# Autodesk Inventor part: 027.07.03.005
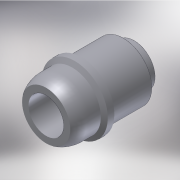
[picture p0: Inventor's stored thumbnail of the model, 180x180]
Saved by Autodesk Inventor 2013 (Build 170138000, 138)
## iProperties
Shininess: 25.0
Length Units: 11269
Angle Units: 11279
Time Units: 11290
Mass Units: 11283
Length Display Precision: 3
Angle Display Precision: 2
Created: 2002-01
Part Number: 027.07.03.005
Document SubType Name: Modeling
Designer: SaAlex
Material: Steel, Mild
Density: 7.86 g/cm^3
Density: 0.0
Volumn: 0.0
Area: 0.0
PropertySet Name: Model Information
Control State: 0
Master: False
Checked Out: False
Checked Out Date: 2008-10-15
Last Check In Date: 2008-10-15
Author: SaAlex
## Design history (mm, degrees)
feature "Base1"
body "Solid1"
